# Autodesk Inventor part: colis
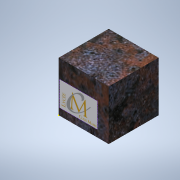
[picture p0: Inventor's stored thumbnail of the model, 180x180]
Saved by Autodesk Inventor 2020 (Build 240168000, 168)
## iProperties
Created: 2021-10
Part Number: colis
Material: Générique
Document SubType Name: Modeling
Designer: bruno
Density: 1 g/cm^3
Appearance: Rouillé
Author: bruno
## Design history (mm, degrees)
sketch "Esquisse1"
  geometry: L1 (0, 0)-(50, 0); L2 (50, 0)-(50, -50); L3 (50, -50)-(0, -50); L4 (0, -50)-(0, 0)
  constraints: 8 end point, 2 parallel, 1 horizontal, 1 perpendicular
  dimensions: "d0" = 50 distance of L2.end L3.end; "d1" = 50 distance of L1.end L2.end
extrude "Extrusion1" new body sketch "Esquisse1" distance "d2" = 50; taper "d3" = 0 deg
sketch "Esquisse2"
  geometry: L1 (6.307, 38.31)-(44.246, 38.31); L2 (44.246, 38.31)-(44.246, 13.421); L3 (44.246, 13.421)-(6.307, 13.421); L4 (6.307, 13.421)-(6.307, 38.31); 1 further point; 1 other entity
  constraints: 2 other
  node "Image1"
sketch "Esquisse3"
  geometry: L1 (-42.641, 43.344)-(-6.099, 43.344); L2 (-6.099, 43.344)-(-6.099, 19.37); L3 (-6.099, 19.37)-(-42.641, 19.37); L4 (-42.641, 19.37)-(-42.641, 43.344); 1 further point; 1 other entity
  constraints: 2 other
  node "Image2"
node "Solide1"
other parameters: "sa_0" = 4
